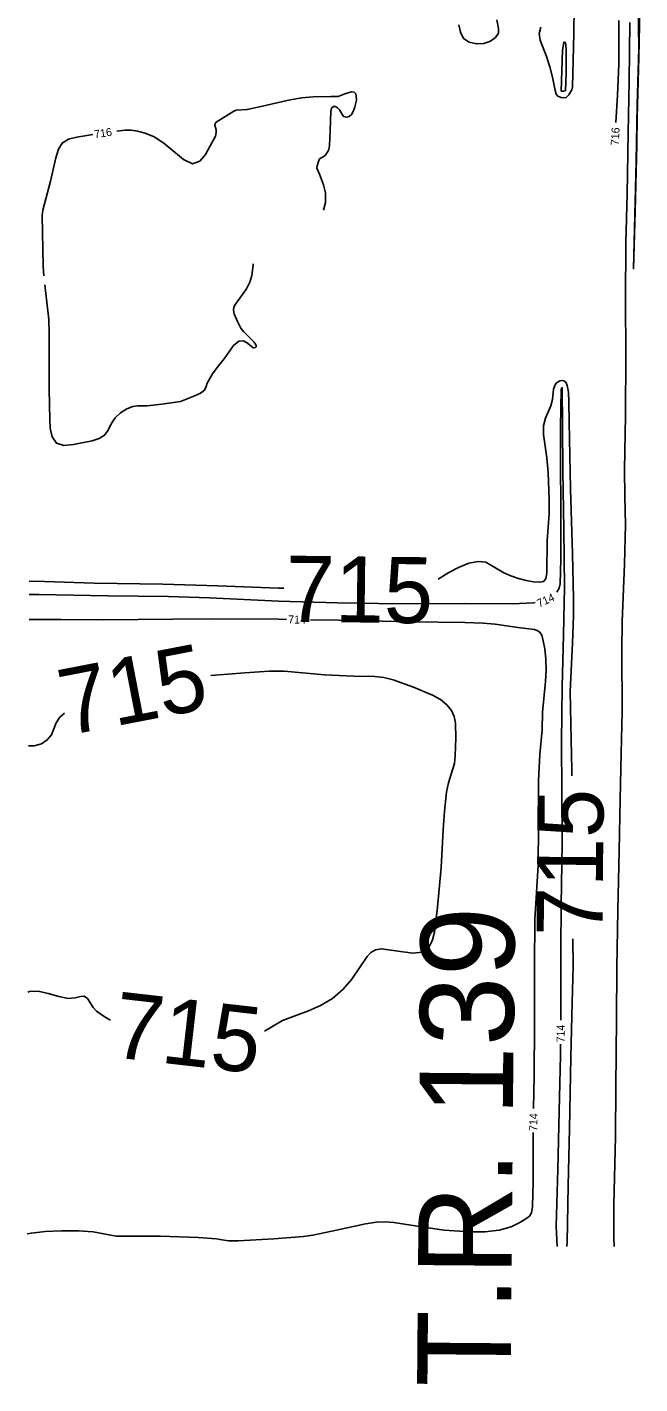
# Model space of a CAD drawing. Extents: x -468556195 to 3353078, y -306091294 to 1252632.
# Drawn here: x 1829446 to 1829752, y 532541 to 533219 of the extents above; entities that cross this region are included whole.
import ezdxf

# ---------------------------------------------------------------- set-up
doc = ezdxf.new("R2010")
doc.units = 0
for name, color, linetype in [('DT_X_Contour_Minor', 7, 'Continuous'), ('Level 19', 7, 'Continuous'), ('Level 40', 7, 'Continuous')]:
    doc.layers.add(name, color=color, linetype=linetype)

msp = doc.modelspace()

# ---------------------------------------------------------------- linework, layer by layer
at = {"layer": 'DT_X_Contour_Minor'}
for points in [[(1829719.45, 533243.53), (1829719.19, 533215.99), (1829718.6, 533189.48), (1829718.2, 533188.02), (1829716.69, 533185.56), (1829715.24, 533184.09), (1829712.9, 533184.25), (1829711.18, 533184.88), (1829710.34, 533185.91), (1829709.91, 533187.77), (1829708.46, 533194.46), (1829707.13, 533199.6), (1829705.5, 533204.75), (1829702.33, 533212.88), (1829701.85, 533216.19), (1829702.64, 533219.42)], [(1829751.18, 533242.54), (1829751.68, 533208.83), (1829750.93, 533180.49), (1829750.4, 533152.32), (1829749.74, 533125.36), (1829749.09, 533098.66), (1829749.16, 533104.57), (1829749.84, 533127.22), (1829750.61, 533160.77), (1829750.84, 533174.52), (1829751.64, 533204.27), (1829752.2, 533228.73)], [(1829680.65, 533223.09), (1829681.6, 533218.75), (1829681.47, 533216.45), (1829680.09, 533214.22), (1829677.58, 533212.37), (1829674.27, 533211.19), (1829670.52, 533210.97), (1829666.92, 533211.81), (1829664.1, 533213.77), (1829662.49, 533216.83), (1829661.73, 533220.54)], [(1829747.24, 533221.66), (1829746.86, 533192.5), (1829746.38, 533166.52), (1829745.85, 533135.9), (1829745.23, 533111.58), (1829745.09, 533082.89), (1829745.24, 533055.57), (1829744.95, 533025.32), (1829744.58, 532998.14), (1829744.71, 532984.96), (1829745.04, 532970.62), (1829744.49, 532950.94), (1829743.36, 532922.2), (1829743.24, 532907.81), (1829743.37, 532877.35), (1829742.82, 532856.39), (1829742.32, 532833.62), (1829741.79, 532807.97), (1829741.18, 532777.91), (1829740.69, 532749.35), (1829740.45, 532723.59), (1829740.23, 532689.72), (1829739.94, 532664.98), (1829739.11, 532630.73), (1829739.14, 532614.28), (1829739.32, 532609.93)], [(1829741.67, 533222.71), (1829741.71, 533200.68), (1829741.01, 533185.42), (1829740.24, 533171.68)], [(1829712.88, 533187.47), (1829713.58, 533207.87), (1829714.15, 533211.76), (1829714.49, 533211.91), (1829714.86, 533211.75), (1829715.2, 533210.68), (1829715.41, 533207.81), (1829715.33, 533196.63), (1829714.99, 533187.56), (1829714.26, 533187.43), (1829712.88, 533187.47)], [(1829593.98, 533127.95), (1829595.08, 533131.72), (1829595, 533136.53), (1829594.12, 533140.65), (1829592.1, 533145.85), (1829590.72, 533148.89), (1829590.94, 533150.04), (1829591.48, 533152.2), (1829592.01, 533153.55), (1829593.48, 533154.36), (1829594.85, 533155.28), (1829596.27, 533157.17), (1829596.76, 533158.27), (1829597.14, 533160.32), (1829597.43, 533167.6), (1829597.67, 533177.31), (1829598.14, 533178.93), (1829598.98, 533179.69), (1829600.04, 533179.71), (1829601.13, 533179.13), (1829602.08, 533178.1), (1829604.13, 533174.76), (1829605.73, 533174.47), (1829606.95, 533174.75), (1829608.13, 533175.71), (1829609.09, 533177.5), (1829609.78, 533179.64), (1829610.57, 533182.92), (1829610.46, 533184.85), (1829610.14, 533186.04), (1829609.35, 533186.88), (1829607.98, 533187.04), (1829604.78, 533186.14), (1829601.42, 533184.75), (1829597.69, 533184.66), (1829588.96, 533184.52), (1829583.29, 533184.02), (1829577.33, 533183.06), (1829562.03, 533179.63), (1829555.85, 533178.26), (1829550.43, 533177.88), (1829549.3, 533177.48), (1829540.49, 533171.97), (1829539.85, 533171.25), (1829539.72, 533170.44), (1829540.39, 533168.14), (1829540.48, 533166.67), (1829540, 533164.96), (1829537.23, 533159.67), (1829535.02, 533155.78), (1829532.17, 533152.39), (1829528.55, 533151.15), (1829524.14, 533153.16), (1829514.19, 533161.45), (1829509.36, 533164.49), (1829504.96, 533166.33), (1829501.15, 533167.34), (1829497.97, 533167.83), (1829494.89, 533167.89), (1829490.68, 533167.38)], [(1829478.8, 533165.67), (1829470.79, 533164.43), (1829466.61, 533163.37), (1829463.49, 533161.48), (1829461.55, 533158.36), (1829460.3, 533154.02), (1829457.53, 533142.47), (1829453.72, 533127.98), (1829453.51, 533125.31), (1829453.96, 533099.92), (1829454.35, 533095.1)], [(1829454.8, 533090.59), (1829456.74, 533073.33), (1829456.88, 533066.24), (1829456.89, 533038.48), (1829457.24, 533023.29), (1829457.51, 533018.9), (1829458.43, 533014.56), (1829460.58, 533011.43), (1829464.33, 533010.37), (1829469.08, 533010.79), (1829478.38, 533012.71), (1829481.97, 533013.76), (1829484.67, 533015.42), (1829486.5, 533017.98), (1829488, 533021.07), (1829489.88, 533024.13), (1829492.61, 533026.7), (1829495.78, 533028.6), (1829498.75, 533029.74), (1829501.11, 533030.12), (1829505.92, 533030.07), (1829513.25, 533030.94), (1829522.55, 533032.36), (1829529.17, 533034.92), (1829532.59, 533036.43), (1829534.61, 533037.89), (1829535.36, 533039.84), (1829535.97, 533041.46), (1829538.58, 533046.12), (1829541.4, 533049.89), (1829544.4, 533053.64), (1829549.11, 533060.21), (1829551.7, 533062.4), (1829554.1, 533062.59), (1829556.13, 533061.45), (1829558.98, 533059.05), (1829560.06, 533059.32), (1829560.37, 533059.61), (1829560.46, 533060.1), (1829560.15, 533060.89), (1829559.26, 533062.05), (1829554.06, 533067.23), (1829552.81, 533068.91), (1829551.11, 533072.26), (1829549.44, 533076.14), (1829549.02, 533077.91), (1829549.19, 533079.38), (1829550, 533080.87), (1829555.52, 533088.61), (1829557.26, 533091.98), (1829558.26, 533095.25), (1829558.83, 533100.51), (1829558.91, 533101.12)], [(1829718.11, 532845.17), (1829718.15, 532848.01), (1829717.79, 532863.39), (1829717.44, 532887.39), (1829718.49, 532911.44), (1829719.06, 532925.16), (1829719.1, 532933.85), (1829718.54, 532956.2), (1829717.51, 532988.59), (1829716.8, 533021.91), (1829716.75, 533032.13), (1829716.48, 533037.02), (1829715.94, 533040.21), (1829715.17, 533041.91), (1829714.26, 533042.63), (1829713.27, 533042.82), (1829712.26, 533042.63), (1829711.28, 533042.14), (1829710.38, 533041.38), (1829709.62, 533040.22), (1829709.1, 533038.5), (1829708.46, 533033.25), (1829707.72, 533030.2), (1829704.99, 533023.9), (1829704.07, 533020.18), (1829704.11, 533015.75), (1829705.66, 533004.1), (1829706.28, 532996.81), (1829706.81, 532983.3), (1829706.79, 532976.13), (1829705.8, 532962.75), (1829705.67, 532946.58), (1829705.18, 532943.65), (1829704.09, 532942.29), (1829702.11, 532941.95), (1829699.09, 532942.15), (1829695.38, 532942.76), (1829691.46, 532943.76), (1829687.71, 532945.09), (1829684.25, 532946.69), (1829675.18, 532951.93), (1829671.47, 532952.4), (1829666.77, 532951.45), (1829661.59, 532949.41), (1829656.65, 532946.79), (1829651.34, 532943.44)], [(1829712.71, 532723.17), (1829712.75, 532725.74), (1829712.72, 532758.63), (1829712.88, 532780.58), (1829713.38, 532811.75), (1829713.23, 532836.82), (1829713.02, 532862.45), (1829713.31, 532889.73), (1829714.02, 532915.75), (1829714.47, 532939.31), (1829714.15, 532968.73), (1829713.66, 532997.33), (1829713.46, 533020.48), (1829713.41, 533039.17), (1829712.99, 533039.02), (1829712.87, 533038.28), (1829712.5, 533019.27), (1829712.45, 533003.81), (1829712.69, 532976.79), (1829712.64, 532953.52), (1829712.33, 532941.15), (1829711.94, 532939.07), (1829710.66, 532937.05)], [(1829574.2, 532938.95), (1829571.59, 532939.01), (1829541.21, 532940.22), (1829513.76, 532941), (1829479.36, 532941.55), (1829454.58, 532942.25), (1829446.94, 532942.45)], [(1829699.86, 532931.82), (1829699.17, 532931.7), (1829688.38, 532931.21), (1829664.72, 532931.27), (1829631.71, 532931.2), (1829601.09, 532931.71), (1829571.55, 532932.48), (1829537.04, 532934.1), (1829516.57, 532934.82), (1829486.19, 532935.21), (1829451.75, 532935.91), (1829446.91, 532935.81)], [(1829446.88, 532923.28), (1829448.52, 532923.35), (1829462.94, 532923.29), (1829483.99, 532923.23), (1829518.76, 532923.56), (1829538.53, 532923.68), (1829571.73, 532923.45), (1829575.62, 532923.39)], [(1829587.61, 532923.2), (1829601.55, 532922.98), (1829637.94, 532922.16), (1829664.63, 532921.83), (1829673.84, 532921.53), (1829679.83, 532921), (1829691.15, 532919.36), (1829699.46, 532918.32), (1829701.86, 532917.31), (1829703.16, 532915.58), (1829703.93, 532912.76), (1829704.63, 532908.65), (1829705.16, 532903.57), (1829705.34, 532898.01), (1829705.05, 532892.37), (1829703.57, 532876.99), (1829703.35, 532868.14), (1829702.2, 532855.82), (1829701.59, 532842.75), (1829701.56, 532819.83), (1829701.31, 532800.54), (1829700.2, 532781.35), (1829699.69, 532773.6), (1829699.56, 532750.03), (1829699.54, 532720.53), (1829699.43, 532695.52), (1829699.1, 532678.88)], [(1829537.69, 532895.38), (1829554.69, 532896.74), (1829566.85, 532897.6), (1829574.33, 532897.51), (1829594.6, 532895.64), (1829609.3, 532894.96), (1829619.72, 532894.83), (1829624.17, 532894.32), (1829628.9, 532893.14), (1829638.97, 532889.55), (1829648.55, 532885.59), (1829652.54, 532883.33), (1829655.69, 532880.75), (1829657.98, 532877.88), (1829659.44, 532874.79), (1829660.12, 532871.53), (1829660.21, 532864.08), (1829659.93, 532855.35), (1829659.47, 532851.45), (1829658.62, 532848.29), (1829656.49, 532841.72), (1829655.61, 532837.02), (1829654.48, 532827.47), (1829653.9, 532818.17), (1829652.91, 532799.43), (1829651.03, 532779.56), (1829649.51, 532767.05), (1829648.58, 532763.18), (1829646.76, 532759.48), (1829643.5, 532757.06), (1829638.53, 532756.64), (1829623.05, 532758.79), (1829620, 532758.23), (1829617.73, 532756.92), (1829615.88, 532754.92), (1829608.2, 532743.65), (1829603.87, 532738.6), (1829598.57, 532733.97), (1829592.48, 532730.37), (1829586.49, 532727.76), (1829573.51, 532723.01), (1829568.31, 532719.73), (1829564.58, 532717.6)], [(1829446.68, 532860.25), (1829449.49, 532860.19), (1829453.03, 532861.24), (1829455.98, 532863.19), (1829458.1, 532865.75), (1829460.41, 532871.65), (1829462.27, 532874.58), (1829464.56, 532876.45)], [(1829715.77, 532610), (1829715.78, 532612.06), (1829716.37, 532640.47), (1829716.96, 532668.9), (1829717.66, 532704.68), (1829718.41, 532731.98), (1829718.84, 532749.94), (1829718.68, 532763.73)], [(1829487.62, 532723.05), (1829484.92, 532724.6), (1829480.6, 532727.66), (1829478.94, 532729.5), (1829476.06, 532733.87), (1829474.5, 532735.07), (1829472.57, 532734.92), (1829469.99, 532734.19), (1829466.43, 532733.94), (1829461.73, 532734.9), (1829456.47, 532736.43), (1829451.41, 532737.52), (1829447.1, 532737.41), (1829446.29, 532737.14)], [(1829710.9, 532610.01), (1829710.42, 532620.17), (1829711.15, 532648.46), (1829711.8, 532677.62), (1829712.45, 532705.49), (1829712.54, 532711.17)], [(1829698.91, 532666.88), (1829698.83, 532642.2), (1829698.54, 532629.94), (1829698.09, 532626.85), (1829697.11, 532625.17), (1829695.26, 532623.79), (1829692.21, 532621.9), (1829687.82, 532619.81), (1829681.95, 532618.14), (1829674.7, 532617.35), (1829666.99, 532617.28), (1829654.4, 532618.15), (1829645.14, 532619.55), (1829629.29, 532621.93), (1829624.88, 532622.27), (1829620.47, 532622.12), (1829615.08, 532621.35), (1829600.6, 532618.21), (1829588.78, 532615.62), (1829584.07, 532614.96), (1829569.2, 532613.79), (1829551.47, 532612.86), (1829546.54, 532612.87), (1829542.49, 532613.49), (1829540.59, 532613.8), (1829531.4, 532614.42), (1829512.58, 532615.18), (1829497.33, 532615.2), (1829490.43, 532615.13), (1829478.92, 532617.3), (1829471.57, 532617.75), (1829463.09, 532617.81), (1829454.87, 532617.46), (1829448.07, 532616.72), (1829445.92, 532616.36)]]:
    msp.add_lwpolyline(points, dxfattribs=at)

# ---------------------------------------------------------------- texts
at = {"layer": 'Level 19'}
for s, height, rotation, p in [('716', 4, 8.83501, (1829479.75, 533163.79)), ('716', 4, 86.78592, (1829741.6, 533160.24)), ('715', 33, 359.33048, (1829575.02, 532922.28)), ('714', 4, 24.33925, (1829701.87, 532929.29)), ('714', 4, 359.09557, (1829576.37, 532921.38)), ('715', 33, 10.96068, (1829465.51, 532865.24)), ('715', 33, 89.57622, (1829733.55, 532764.99)), ('715', 33, 353.47485, (1829487.75, 532704.7)), ('714', 4, 89.15796, (1829714.55, 532711.92)), ('714', 4, 88.84284, (1829700.87, 532667.63))]:
    msp.add_text(s, height=height, rotation=rotation, dxfattribs=at).set_placement(p)
at = {"layer": 'Level 40'}
msp.add_text('T.R. 139', height=46.8, rotation=89.52618, dxfattribs=at).set_placement((1829687.61, 532539.58))

doc.saveas('drawing.dxf')
